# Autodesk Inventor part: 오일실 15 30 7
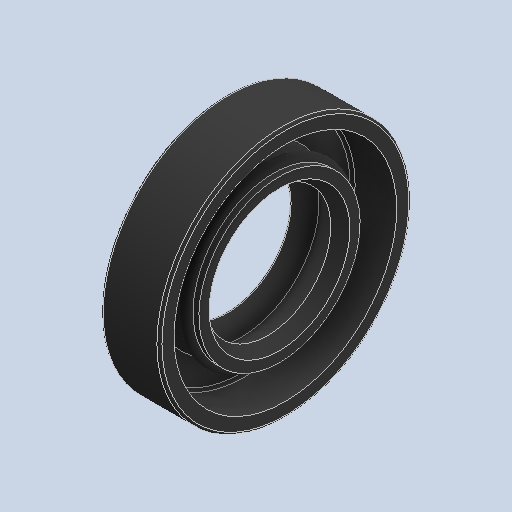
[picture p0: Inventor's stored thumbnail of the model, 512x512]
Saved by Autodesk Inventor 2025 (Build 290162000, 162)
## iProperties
Created: 2024-07
Part Number: 오일실 15 30 7
Material: 고무
Description: 오일-실
Document SubType Name: Modeling
Designer: deana
Density: 0.93 g/cm^3
Appearance: 기본값
Author: jhkim
Sending System: Autodesk Inventor 2025
Preprocessor: ST-DEVELOPER v20
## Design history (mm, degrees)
feature "Solid1"
node "솔리드1"
